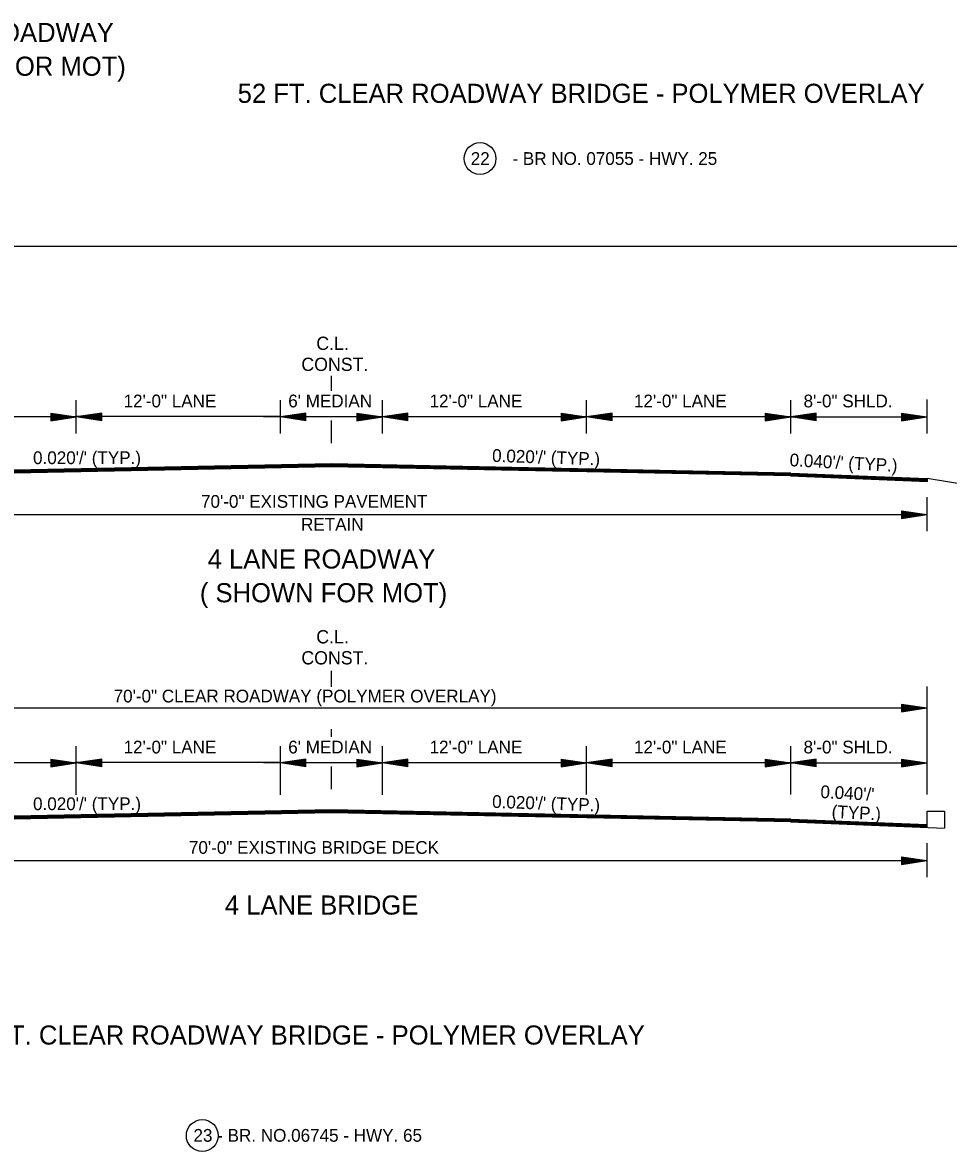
# Model space of a CAD drawing. Extents: x 550980 to 1930787, y -1972975 to 596640.
# Drawn here: x 551373 to 551917, y -1956599 to -1955935 of the extents above; entities that cross this region are included whole.
import ezdxf

# ---------------------------------------------------------------- set-up
doc = ezdxf.new("R2010")
doc.units = 0
doc.layers.add('R_Border', color=7, linetype='Continuous')
doc.layers.add('R_Draft', color=7, linetype='Continuous')

# ---------------------------------------------------------------- blocks, each defined once
blk = doc.blocks.new('BPPOLY')
at = {"layer": 'R_Border'}
blk.add_circle((0, 0), 9.34, dxfattribs=at)

msp = doc.modelspace()

# ---------------------------------------------------------------- linework, layer by layer
at = {"layer": 'R_Border'}
for p, q in [((551025.9, -1956066.24), (552087.17, -1956066.24)), ((551904.55, -1956407.84), (551904.55, -1956398.43)), ((551904.55, -1956398.43), (551914.71, -1956398.43)), ((551914.71, -1956398.43), (551914.71, -1956408.44))]:
    msp.add_line(p, q, dxfattribs=at)
msp.add_circle((551478.34, -1956589.22), 9.34, dxfattribs=at)
at = {"layer": 'R_Draft'}
for p, q in [((551554.29, -1956146.86), (551554.29, -1956142.45)), ((551554.29, -1956151.23), (551554.29, -1956146.86)), ((551404.29, -1956176.45), (551404.29, -1956156.73)), ((551524.29, -1956176.45), (551524.29, -1956156.73)), ((551584.21, -1956166.62), (551584.21, -1956156.73)), ((551584.29, -1956176.45), (551584.29, -1956156.73)), ((551704.29, -1956176.45), (551704.29, -1956156.73)), ((551824.29, -1956176.45), (551824.29, -1956156.73)), ((551404.29, -1956166.62), (551284.29, -1956166.62)), ((551389.29, -1956164.37), (551404.29, -1956166.62)), ((551389.29, -1956164.37), (551389.29, -1956168.87)), ((551389.29, -1956164.75), (551401.78, -1956166.62)), ((551389.29, -1956165.13), (551399.2, -1956166.62)), ((551389.29, -1956165.51), (551396.7, -1956166.62)), ((551389.29, -1956165.9), (551394.16, -1956166.62)), ((551389.29, -1956166.27), (551391.66, -1956166.62)), ((551389.29, -1956168.87), (551404.29, -1956166.62)), ((551389.29, -1956167.36), (551394.16, -1956166.62)), ((551389.29, -1956168.12), (551399.2, -1956166.62)), ((551389.29, -1956168.5), (551401.78, -1956166.62)), ((551389.29, -1956167.74), (551396.7, -1956166.62)), ((551389.29, -1956166.98), (551391.66, -1956166.62)), ((551419.29, -1956164.37), (551404.29, -1956166.62)), ((551524.29, -1956166.45), (551404.29, -1956166.45)), ((551419.29, -1956168.87), (551404.29, -1956166.62)), ((551419.29, -1956164.75), (551406.79, -1956166.62)), ((551419.29, -1956168.5), (551406.79, -1956166.62)), ((551419.29, -1956165.13), (551409.37, -1956166.62)), ((551419.29, -1956168.12), (551409.37, -1956166.62)), ((551419.29, -1956165.51), (551411.87, -1956166.62)), ((551419.29, -1956167.74), (551411.87, -1956166.62)), ((551419.29, -1956165.89), (551414.41, -1956166.62)), ((551419.29, -1956167.35), (551414.41, -1956166.62)), ((551419.29, -1956166.27), (551416.92, -1956166.62)), ((551419.29, -1956166.98), (551416.92, -1956166.62)), ((551419.29, -1956168.87), (551419.29, -1956164.37)), ((551584.29, -1956166.62), (551514.29, -1956166.62)), ((551539.29, -1956164.37), (551524.29, -1956166.62)), ((551539.29, -1956168.87), (551524.29, -1956166.62)), ((551539.29, -1956164.75), (551526.79, -1956166.62)), ((551539.29, -1956168.5), (551526.79, -1956166.62)), ((551539.29, -1956165.13), (551529.37, -1956166.62)), ((551539.29, -1956168.12), (551529.37, -1956166.62)), ((551539.29, -1956165.51), (551531.87, -1956166.62)), ((551539.29, -1956167.74), (551531.87, -1956166.62)), ((551539.29, -1956165.89), (551534.41, -1956166.62)), ((551539.29, -1956167.35), (551534.41, -1956166.62)), ((551539.29, -1956166.27), (551536.92, -1956166.62)), ((551539.29, -1956166.98), (551536.92, -1956166.62)), ((551539.29, -1956168.87), (551539.29, -1956164.37)), ((551554.29, -1956182.03), (551554.29, -1956168.74)), ((551569.29, -1956164.37), (551584.29, -1956166.62)), ((551569.29, -1956164.37), (551569.29, -1956168.87)), ((551569.29, -1956164.75), (551581.78, -1956166.62)), ((551569.29, -1956165.13), (551579.2, -1956166.62)), ((551569.29, -1956165.51), (551576.7, -1956166.62)), ((551569.29, -1956165.9), (551574.16, -1956166.62)), ((551569.29, -1956166.27), (551571.66, -1956166.62)), ((551569.29, -1956168.87), (551584.29, -1956166.62)), ((551569.29, -1956167.36), (551574.16, -1956166.62)), ((551569.29, -1956168.12), (551579.2, -1956166.62)), ((551569.29, -1956168.5), (551581.78, -1956166.62)), ((551569.29, -1956167.74), (551576.7, -1956166.62)), ((551569.29, -1956166.98), (551571.66, -1956166.62)), ((551584.21, -1956176.45), (551584.21, -1956166.62)), ((551599.29, -1956164.37), (551584.29, -1956166.62)), ((551704.29, -1956166.62), (551584.29, -1956166.62)), ((551599.29, -1956168.87), (551584.29, -1956166.62)), ((551599.29, -1956164.75), (551586.79, -1956166.62)), ((551599.29, -1956168.5), (551586.79, -1956166.62)), ((551599.29, -1956165.13), (551589.37, -1956166.62)), ((551599.29, -1956168.12), (551589.37, -1956166.62)), ((551599.29, -1956165.51), (551591.87, -1956166.62)), ((551599.29, -1956167.74), (551591.87, -1956166.62)), ((551599.29, -1956165.89), (551594.41, -1956166.62)), ((551599.29, -1956167.35), (551594.41, -1956166.62)), ((551599.29, -1956166.27), (551596.92, -1956166.62)), ((551599.29, -1956166.98), (551596.92, -1956166.62)), ((551599.29, -1956168.87), (551599.29, -1956164.37)), ((551689.29, -1956164.37), (551704.29, -1956166.62)), ((551689.29, -1956164.37), (551689.29, -1956168.87)), ((551689.29, -1956164.75), (551701.78, -1956166.62)), ((551689.29, -1956165.13), (551699.2, -1956166.62)), ((551689.29, -1956165.51), (551696.7, -1956166.62)), ((551689.29, -1956165.9), (551694.16, -1956166.62)), ((551689.29, -1956166.27), (551691.66, -1956166.62)), ((551689.29, -1956168.87), (551704.29, -1956166.62)), ((551689.29, -1956167.36), (551694.16, -1956166.62)), ((551689.29, -1956168.12), (551699.2, -1956166.62)), ((551689.29, -1956168.5), (551701.78, -1956166.62)), ((551689.29, -1956167.74), (551696.7, -1956166.62)), ((551689.29, -1956166.98), (551691.66, -1956166.62)), ((551719.29, -1956164.37), (551704.29, -1956166.62)), ((551719.29, -1956168.87), (551704.29, -1956166.62)), ((551824.29, -1956166.62), (551704.29, -1956166.62)), ((551719.29, -1956164.75), (551706.79, -1956166.62)), ((551719.29, -1956168.5), (551706.79, -1956166.62)), ((551719.29, -1956165.13), (551709.37, -1956166.62)), ((551719.29, -1956168.12), (551709.37, -1956166.62)), ((551719.29, -1956165.51), (551711.87, -1956166.62)), ((551719.29, -1956167.74), (551711.87, -1956166.62)), ((551719.29, -1956165.89), (551714.41, -1956166.62)), ((551719.29, -1956167.35), (551714.41, -1956166.62)), ((551719.29, -1956166.27), (551716.92, -1956166.62)), ((551719.29, -1956166.98), (551716.92, -1956166.62)), ((551719.29, -1956168.87), (551719.29, -1956164.37)), ((551809.29, -1956164.37), (551824.29, -1956166.62)), ((551809.29, -1956164.37), (551809.29, -1956168.87)), ((551809.29, -1956164.75), (551821.78, -1956166.62)), ((551809.29, -1956165.13), (551819.2, -1956166.62)), ((551809.29, -1956165.51), (551816.7, -1956166.62)), ((551809.29, -1956165.9), (551814.16, -1956166.62)), ((551809.29, -1956166.27), (551811.66, -1956166.62)), ((551809.29, -1956168.87), (551824.29, -1956166.62)), ((551809.29, -1956167.36), (551814.16, -1956166.62)), ((551809.29, -1956168.12), (551819.2, -1956166.62)), ((551809.29, -1956168.5), (551821.78, -1956166.62)), ((551809.29, -1956167.74), (551816.7, -1956166.62)), ((551809.29, -1956166.98), (551811.66, -1956166.62)), ((551839.29, -1956164.37), (551824.29, -1956166.62)), ((551824.29, -1956166.62), (551904.29, -1956166.62)), ((551839.29, -1956168.87), (551824.29, -1956166.62)), ((551839.29, -1956164.75), (551826.79, -1956166.62)), ((551839.29, -1956168.5), (551826.79, -1956166.62)), ((551839.29, -1956165.13), (551829.37, -1956166.62)), ((551839.29, -1956168.12), (551829.37, -1956166.62)), ((551839.29, -1956165.51), (551831.87, -1956166.62)), ((551839.29, -1956167.74), (551831.87, -1956166.62)), ((551839.29, -1956165.89), (551834.41, -1956166.62)), ((551839.29, -1956167.35), (551834.41, -1956166.62)), ((551839.29, -1956166.27), (551836.92, -1956166.62)), ((551839.29, -1956166.98), (551836.92, -1956166.62)), ((551839.29, -1956168.87), (551839.29, -1956164.37)), ((551889.29, -1956164.37), (551904.29, -1956166.62)), ((551889.29, -1956164.37), (551889.29, -1956168.87)), ((551889.29, -1956164.75), (551901.78, -1956166.62)), ((551889.29, -1956165.13), (551899.2, -1956166.62)), ((551889.29, -1956165.51), (551896.7, -1956166.62)), ((551889.29, -1956165.9), (551894.16, -1956166.62)), ((551889.29, -1956166.27), (551891.66, -1956166.62)), ((551889.29, -1956168.87), (551904.29, -1956166.62)), ((551889.29, -1956167.36), (551894.16, -1956166.62)), ((551889.29, -1956168.12), (551899.2, -1956166.62)), ((551889.29, -1956168.5), (551901.78, -1956166.62)), ((551889.29, -1956167.74), (551896.7, -1956166.62)), ((551889.29, -1956166.98), (551891.66, -1956166.62)), ((551554.29, -1956194.23), (551284.29, -1956199.63)), ((551554.29, -1956194.53), (551284.29, -1956199.93)), ((551554.3, -1956194.83), (551284.29, -1956200.23)), ((551554.3, -1956195.13), (551284.29, -1956200.53)), ((551554.31, -1956195.43), (551284.29, -1956200.83)), ((551554.32, -1956195.73), (551284.29, -1956201.13)), ((551554.32, -1956195.93), (551284.29, -1956201.33)), ((551824.29, -1956201.33), (551554.25, -1956195.93)), ((551824.29, -1956200.83), (551554.26, -1956195.43)), ((551824.29, -1956201.13), (551554.26, -1956195.73)), ((551824.29, -1956200.23), (551554.27, -1956194.83)), ((551824.29, -1956200.53), (551554.27, -1956195.13)), ((551824.29, -1956199.93), (551554.28, -1956194.53)), ((551824.29, -1956199.63), (551554.29, -1956194.23)), ((551824.22, -1956201.33), (551904.56, -1956204.54)), ((551824.23, -1956201.13), (551904.55, -1956204.34)), ((551824.24, -1956200.83), (551904.55, -1956204.04)), ((551824.25, -1956200.53), (551904.55, -1956203.74)), ((551824.26, -1956200.23), (551904.55, -1956203.44)), ((551824.27, -1956199.93), (551904.55, -1956203.14)), ((551824.29, -1956199.63), (551904.55, -1956202.84)), ((552004.61, -1956219.52), (551904.55, -1956202.84)), ((551904.55, -1956202.84), (551904.55, -1956204.54)), ((551904.29, -1956213.84), (551904.29, -1956233.84)), ((551889.29, -1956221.84), (551904.29, -1956224.09)), ((551889.29, -1956221.84), (551889.29, -1956226.34)), ((551889.29, -1956222.21), (551901.78, -1956224.09)), ((551889.29, -1956222.6), (551899.2, -1956224.09)), ((551889.29, -1956222.97), (551896.7, -1956224.09)), ((551204.25, -1956224.09), (551904.29, -1956224.09)), ((551889.29, -1956223.36), (551894.16, -1956224.09)), ((551889.29, -1956223.74), (551891.66, -1956224.09)), ((551889.29, -1956226.34), (551904.29, -1956224.09)), ((551889.29, -1956224.82), (551894.16, -1956224.09)), ((551889.29, -1956225.58), (551899.2, -1956224.09)), ((551889.29, -1956225.96), (551901.78, -1956224.09)), ((551889.29, -1956225.21), (551896.7, -1956224.09)), ((551889.29, -1956224.44), (551891.66, -1956224.09)), ((551554.29, -1956325.29), (551554.29, -1956315.99)), ((551889.32, -1956335.51), (551904.32, -1956337.76)), ((551889.32, -1956335.51), (551889.32, -1956340.01)), ((551889.32, -1956335.88), (551901.82, -1956337.76)), ((551204.25, -1956337.76), (551904.29, -1956337.76)), ((551889.32, -1956336.26), (551899.24, -1956337.76)), ((551889.32, -1956336.64), (551896.74, -1956337.76)), ((551889.32, -1956337.03), (551894.2, -1956337.76)), ((551889.32, -1956337.4), (551891.69, -1956337.76)), ((551889.32, -1956340.01), (551904.32, -1956337.76)), ((551889.32, -1956338.49), (551894.2, -1956337.76)), ((551889.32, -1956339.25), (551899.24, -1956337.76)), ((551889.32, -1956339.63), (551901.82, -1956337.76)), ((551889.32, -1956338.87), (551896.74, -1956337.76)), ((551889.32, -1956338.11), (551891.69, -1956337.76)), ((551554.29, -1956354.73), (551554.29, -1956350.35)), ((551404.29, -1956388.78), (551404.29, -1956360.23)), ((551524.29, -1956388.78), (551524.29, -1956360.23)), ((551584.21, -1956370.12), (551584.21, -1956360.23)), ((551584.29, -1956388.78), (551584.29, -1956360.23)), ((551704.29, -1956388.77), (551704.29, -1956360.22)), ((551824.29, -1956388.77), (551824.29, -1956360.22)), ((551389.29, -1956367.87), (551404.29, -1956370.12)), ((551389.29, -1956367.87), (551389.29, -1956372.37)), ((551389.29, -1956368.24), (551401.78, -1956370.12)), ((551389.29, -1956368.63), (551399.2, -1956370.12)), ((551389.29, -1956369), (551396.7, -1956370.12)), ((551419.29, -1956367.87), (551404.29, -1956370.12)), ((551419.29, -1956368.24), (551406.79, -1956370.12)), ((551419.29, -1956368.63), (551409.37, -1956370.12)), ((551419.29, -1956369), (551411.87, -1956370.12)), ((551419.29, -1956372.37), (551419.29, -1956367.87)), ((551539.29, -1956367.87), (551524.29, -1956370.12)), ((551539.29, -1956368.24), (551526.79, -1956370.12)), ((551539.29, -1956368.63), (551529.37, -1956370.12)), ((551539.29, -1956369), (551531.87, -1956370.12)), ((551539.29, -1956372.37), (551539.29, -1956367.87)), ((551569.29, -1956367.87), (551584.29, -1956370.12)), ((551569.29, -1956367.87), (551569.29, -1956372.37)), ((551569.29, -1956368.24), (551581.78, -1956370.12)), ((551569.29, -1956368.63), (551579.2, -1956370.12)), ((551569.29, -1956369), (551576.7, -1956370.12)), ((551599.29, -1956367.87), (551584.29, -1956370.12)), ((551599.29, -1956368.24), (551586.79, -1956370.12)), ((551599.29, -1956368.63), (551589.37, -1956370.12)), ((551599.29, -1956369), (551591.87, -1956370.12)), ((551599.29, -1956372.37), (551599.29, -1956367.87)), ((551689.29, -1956367.87), (551704.29, -1956370.12)), ((551689.29, -1956367.87), (551689.29, -1956372.37)), ((551689.29, -1956368.24), (551701.78, -1956370.12)), ((551689.29, -1956368.63), (551699.2, -1956370.12)), ((551689.29, -1956369), (551696.7, -1956370.12)), ((551719.29, -1956367.87), (551704.29, -1956370.12)), ((551719.29, -1956368.24), (551706.79, -1956370.12)), ((551719.29, -1956368.63), (551709.37, -1956370.12)), ((551719.29, -1956369), (551711.87, -1956370.12)), ((551719.29, -1956372.37), (551719.29, -1956367.87)), ((551809.29, -1956367.87), (551824.29, -1956370.12)), ((551809.29, -1956367.87), (551809.29, -1956372.37)), ((551809.29, -1956368.24), (551821.78, -1956370.12)), ((551809.29, -1956368.63), (551819.2, -1956370.12)), ((551809.29, -1956369), (551816.7, -1956370.12)), ((551839.29, -1956367.87), (551824.29, -1956370.12)), ((551839.29, -1956368.24), (551826.79, -1956370.12)), ((551839.29, -1956368.63), (551829.37, -1956370.12)), ((551839.29, -1956369), (551831.87, -1956370.12)), ((551839.29, -1956372.37), (551839.29, -1956367.87)), ((551889.29, -1956367.87), (551904.29, -1956370.12)), ((551889.29, -1956367.87), (551889.29, -1956372.37)), ((551889.29, -1956368.24), (551901.78, -1956370.12)), ((551889.29, -1956368.63), (551899.2, -1956370.12)), ((551889.29, -1956369), (551896.7, -1956370.12)), ((551404.29, -1956370.12), (551284.29, -1956370.12)), ((551389.29, -1956369.39), (551394.16, -1956370.12)), ((551389.29, -1956369.77), (551391.66, -1956370.12)), ((551389.29, -1956372.37), (551404.29, -1956370.12)), ((551389.29, -1956370.85), (551394.16, -1956370.12)), ((551389.29, -1956371.61), (551399.2, -1956370.12)), ((551389.29, -1956371.99), (551401.78, -1956370.12)), ((551389.29, -1956371.24), (551396.7, -1956370.12)), ((551389.29, -1956370.47), (551391.66, -1956370.12)), ((551524.29, -1956369.95), (551404.29, -1956369.95)), ((551419.29, -1956372.37), (551404.29, -1956370.12)), ((551419.29, -1956371.99), (551406.79, -1956370.12)), ((551419.29, -1956371.61), (551409.37, -1956370.12)), ((551419.29, -1956371.24), (551411.87, -1956370.12)), ((551419.29, -1956369.38), (551414.41, -1956370.12)), ((551419.29, -1956370.85), (551414.41, -1956370.12)), ((551419.29, -1956369.77), (551416.92, -1956370.12)), ((551419.29, -1956370.47), (551416.92, -1956370.12)), ((551584.29, -1956370.12), (551514.29, -1956370.12)), ((551539.29, -1956372.37), (551524.29, -1956370.12)), ((551539.29, -1956371.99), (551526.79, -1956370.12)), ((551539.29, -1956371.61), (551529.37, -1956370.12)), ((551539.29, -1956371.24), (551531.87, -1956370.12)), ((551539.29, -1956369.38), (551534.41, -1956370.12)), ((551539.29, -1956370.85), (551534.41, -1956370.12)), ((551539.29, -1956369.77), (551536.92, -1956370.12)), ((551539.29, -1956370.47), (551536.92, -1956370.12)), ((551554.29, -1956385.52), (551554.29, -1956372.23)), ((551569.29, -1956369.39), (551574.16, -1956370.12)), ((551569.29, -1956369.77), (551571.66, -1956370.12)), ((551569.29, -1956372.37), (551584.29, -1956370.12)), ((551569.29, -1956370.85), (551574.16, -1956370.12)), ((551569.29, -1956371.61), (551579.2, -1956370.12)), ((551569.29, -1956371.99), (551581.78, -1956370.12)), ((551569.29, -1956371.24), (551576.7, -1956370.12)), ((551569.29, -1956370.47), (551571.66, -1956370.12)), ((551584.21, -1956388.78), (551584.21, -1956370.12)), ((551704.29, -1956370.12), (551584.29, -1956370.12)), ((551599.29, -1956372.37), (551584.29, -1956370.12)), ((551599.29, -1956371.99), (551586.79, -1956370.12)), ((551599.29, -1956371.61), (551589.37, -1956370.12)), ((551599.29, -1956371.24), (551591.87, -1956370.12)), ((551599.29, -1956369.38), (551594.41, -1956370.12)), ((551599.29, -1956370.85), (551594.41, -1956370.12)), ((551599.29, -1956369.77), (551596.92, -1956370.12)), ((551599.29, -1956370.47), (551596.92, -1956370.12)), ((551689.29, -1956369.39), (551694.16, -1956370.12)), ((551689.29, -1956369.77), (551691.66, -1956370.12)), ((551689.29, -1956372.37), (551704.29, -1956370.12)), ((551689.29, -1956370.85), (551694.16, -1956370.12)), ((551689.29, -1956371.61), (551699.2, -1956370.12)), ((551689.29, -1956371.99), (551701.78, -1956370.12)), ((551689.29, -1956371.24), (551696.7, -1956370.12)), ((551689.29, -1956370.47), (551691.66, -1956370.12)), ((551719.29, -1956372.37), (551704.29, -1956370.12)), ((551824.29, -1956370.12), (551704.29, -1956370.12)), ((551719.29, -1956371.99), (551706.79, -1956370.12)), ((551719.29, -1956371.61), (551709.37, -1956370.12)), ((551719.29, -1956371.24), (551711.87, -1956370.12)), ((551719.29, -1956369.38), (551714.41, -1956370.12)), ((551719.29, -1956370.85), (551714.41, -1956370.12)), ((551719.29, -1956369.77), (551716.92, -1956370.12)), ((551719.29, -1956370.47), (551716.92, -1956370.12)), ((551809.29, -1956369.39), (551814.16, -1956370.12)), ((551809.29, -1956369.77), (551811.66, -1956370.12)), ((551809.29, -1956372.37), (551824.29, -1956370.12)), ((551809.29, -1956370.85), (551814.16, -1956370.12)), ((551809.29, -1956371.61), (551819.2, -1956370.12)), ((551809.29, -1956371.99), (551821.78, -1956370.12)), ((551809.29, -1956371.24), (551816.7, -1956370.12)), ((551809.29, -1956370.47), (551811.66, -1956370.12)), ((551824.29, -1956370.12), (551904.29, -1956370.12)), ((551839.29, -1956372.37), (551824.29, -1956370.12)), ((551839.29, -1956371.99), (551826.79, -1956370.12)), ((551839.29, -1956371.61), (551829.37, -1956370.12)), ((551839.29, -1956371.24), (551831.87, -1956370.12)), ((551839.29, -1956369.38), (551834.41, -1956370.12)), ((551839.29, -1956370.85), (551834.41, -1956370.12)), ((551839.29, -1956369.77), (551836.92, -1956370.12)), ((551839.29, -1956370.47), (551836.92, -1956370.12)), ((551889.29, -1956369.39), (551894.16, -1956370.12)), ((551889.29, -1956369.77), (551891.66, -1956370.12)), ((551889.29, -1956372.37), (551904.29, -1956370.12)), ((551889.29, -1956370.85), (551894.16, -1956370.12)), ((551889.29, -1956371.61), (551899.2, -1956370.12)), ((551889.29, -1956371.99), (551901.78, -1956370.12)), ((551889.29, -1956371.24), (551896.7, -1956370.12)), ((551889.29, -1956370.47), (551891.66, -1956370.12)), ((551554.29, -1956397.72), (551284.29, -1956403.12)), ((551554.29, -1956398.02), (551284.29, -1956403.42)), ((551554.3, -1956398.32), (551284.29, -1956403.72)), ((551554.3, -1956398.62), (551284.29, -1956404.02)), ((551554.31, -1956398.92), (551284.29, -1956404.32)), ((551554.32, -1956399.22), (551284.29, -1956404.62)), ((551554.32, -1956399.42), (551284.29, -1956404.82)), ((551824.29, -1956404.82), (551554.25, -1956399.42)), ((551824.29, -1956404.32), (551554.26, -1956398.92)), ((551824.29, -1956404.62), (551554.26, -1956399.22)), ((551824.29, -1956403.72), (551554.27, -1956398.32)), ((551824.29, -1956404.02), (551554.27, -1956398.62)), ((551824.29, -1956403.42), (551554.28, -1956398.02)), ((551824.29, -1956403.12), (551554.29, -1956397.72)), ((551824.22, -1956404.82), (551914.71, -1956408.44)), ((551824.23, -1956404.62), (551904.55, -1956407.84)), ((551824.24, -1956404.32), (551904.55, -1956407.53)), ((551824.25, -1956404.02), (551904.55, -1956407.23)), ((551824.26, -1956403.72), (551904.55, -1956406.93)), ((551824.27, -1956403.42), (551904.55, -1956406.63)), ((551824.29, -1956403.12), (551904.55, -1956406.33)), ((551904.29, -1956417.33), (551904.29, -1956437.33)), ((551204.25, -1956427.58), (551904.29, -1956427.58)), ((551889.29, -1956425.33), (551904.29, -1956427.58)), ((551889.29, -1956425.33), (551889.29, -1956429.83)), ((551889.29, -1956425.71), (551901.78, -1956427.58)), ((551889.29, -1956426.09), (551899.2, -1956427.58)), ((551889.29, -1956426.46), (551896.7, -1956427.58)), ((551889.29, -1956426.85), (551894.16, -1956427.58)), ((551889.29, -1956427.23), (551891.66, -1956427.58)), ((551889.29, -1956429.83), (551904.29, -1956427.58)), ((551889.29, -1956428.32), (551894.16, -1956427.58)), ((551889.29, -1956429.07), (551899.2, -1956427.58)), ((551889.29, -1956429.46), (551901.78, -1956427.58)), ((551889.29, -1956428.7), (551896.7, -1956427.58)), ((551889.29, -1956427.93), (551891.66, -1956427.58))]:
    msp.add_line(p, q, dxfattribs=at)
for points in [[(551904.29, -1956156.45), (551904.29, -1956176.45)], [(551904.29, -1956325.15), (551904.29, -1956388.77)]]:
    msp.add_lwpolyline(points, dxfattribs=at)

# ---------------------------------------------------------------- block references
at = {"layer": 'R_Border'}
msp.add_blockref('BPPOLY', (551641.67, -1956014.7), dxfattribs=at)

# ---------------------------------------------------------------- texts
for s, height, p in [('( SHOWN FOR MOT)', 11.25, (551288.03, -1955966.03)), ('52 FT. CLEAR ROADWAY BRIDGE - POLYMER OVERLAY', 11.25, (551499.19, -1955981.97)), ('22', 7.5, (551636.18, -1956018.45)), ('- BR NO. 07055 - HWY. 25', 7.5, (551660.67, -1956018.45)), ('( SHOWN FOR MOT)', 11.25, (551476.94, -1956275.65))]:
    msp.add_text(s, height=height, dxfattribs=at).set_placement(p)
at = {"layer": 'R_Draft'}
for s, height, p in [('3 LANE ROADWAY', 11.25, (551292.64, -1955946.17)), ('C.L.', 7.8, (551545.39, -1956127.25)), ('CONST.', 7.8, (551536.61, -1956139.61)), ('12\'-0" LANE', 7.5, (551432.1, -1956161.02)), ("6' MEDIAN", 7.5, (551528.89, -1956161.02)), ('12\'-0" LANE', 7.5, (551611.97, -1956161.02)), ('12\'-0" LANE', 7.5, (551732.1, -1956161.02)), ('8\'-0" SHLD.', 7.5, (551831.81, -1956161.02)), ("0.020'/' (TYP.)", 7.5, (551378.89, -1956194.38)), ('70\'-0" EXISTING PAVEMENT', 7.5, (551477.63, -1956220.07)), ('RETAIN', 7.5, (551536.44, -1956233.58)), ('4 LANE ROADWAY', 11.25, (551481.56, -1956255.8)), ('C.L.', 7.8, (551545.39, -1956299.82)), ('CONST.', 7.8, (551536.61, -1956312.19)), ('70\'-0" CLEAR ROADWAY (POLYMER OVERLAY)', 7.5, (551426.26, -1956334.54)), ('12\'-0" LANE', 7.5, (551432.1, -1956364.52)), ("6' MEDIAN", 7.5, (551528.89, -1956364.52)), ('12\'-0" LANE', 7.5, (551611.97, -1956364.52)), ('12\'-0" LANE', 7.5, (551732.1, -1956364.52)), ('8\'-0" SHLD.', 7.5, (551831.81, -1956364.52)), ("0.020'/' (TYP.)", 7.5, (551378.89, -1956397.87)), ('70\'-0" EXISTING BRIDGE DECK', 7.5, (551470.51, -1956423.56)), ('4 LANE BRIDGE', 11.25, (551491.66, -1956459.29)), ('70 FT. CLEAR ROADWAY BRIDGE - POLYMER OVERLAY', 11.25, (551334.7, -1956535.73)), ('23 - BR. NO.06745 - HWY. 65', 7.5, (551473.19, -1956592.86))]:
    msp.add_text(s, height=height, dxfattribs=at).set_placement(p)
for s, rotation, p in [("0.020'/' (TYP.)", 358.06067, (551648.64, -1956193.01)), ("0.040'/' (TYP.)", 356.93347, (551823.46, -1956195.59)), ("0.020'/' (TYP.)", 358.06067, (551648.64, -1956396.5)), ("0.040'/' ", 356.93347, (551841.57, -1956390.7)), ('(TYP.)', 356.93347, (551848.16, -1956402.32))]:
    msp.add_text(s, height=7.5, rotation=rotation, dxfattribs=at).set_placement(p)

doc.saveas('drawing.dxf')
